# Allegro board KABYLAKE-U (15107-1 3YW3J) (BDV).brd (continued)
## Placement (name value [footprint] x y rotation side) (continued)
C410  SC22U6D3V3MX-1-DL-GP  [C603H40]  139.1 136.65 0 bottom
C411  SCD1U16V2KX-3DLGP  [C402H22]  175.42 135.51 180 bottom
C412  SC2D2U10V3KX-1DLGP-U  [C603H36]  145.96 130.05 0 bottom
C413  SC2D2U10V3KX-1DLGP-U  [C603H36]  131.35 129.92 0 bottom
C414  SCD1U16V2KX-3DLGP  [C402H22]  146.97 129.92 0 bottom
C415  SCD1U16V2KX-3DLGP  [C402H22]  130.59 126.62 180 bottom
C416  SC220P50V2KX-3DLGP  [C402H22]  106.97 126.11 270 bottom
C417  SCD1U16V2KX-3DLGP  [C402H22]  140.88 126.11 90 bottom
C418  SCD1U16V2KX-3DLGP  [C402H22]  128.81 125.73 180 bottom
C419  SCD1U16V2KX-3DLGP  [C402H22]  127.92 125.73 180 bottom
C420  SC4D7U6D3V3KX-DLGP  [C603H36]  140.88 125.09 90 bottom
C421  SC4D7U6D3V3KX-DLGP  [C603H36]  153.83 124.97 180 bottom
C422  SCD1U16V2KX-3DLGP  [C402H22]  152.81 124.84 180 bottom
C423  SCD1U16V2KX-3DLGP  [C402H22]  146.85 124.84 0 bottom
C424  SCD1U16V2KX-3DLGP  [C402H22]  145.96 124.84 0 bottom
C425  SCD01U50V2KX-1DLGP  [C402H22]  57.56 119.76 270 bottom
C426  SC10U6D3V3MX-DL-GP  [C603H36]  49.94 118.75 0 bottom
C427  SC1KP50V2KX-1DLGP  [C402H22]  60.1 118.36 0 bottom
C428  SC1U50V3KX-1-GP  [C603H36]  53.63 118.75 0 bottom
C429  SC1U50V3KX-1-GP  [C603H36]  52.36 118.75 0 bottom
C430  SCD1U16V2KX-3DLGP  [C402H22]  47.4 116.71 90 bottom
C431  SCD1U16V2KX-3DLGP  [C402H22]  47.4 115.82 90 bottom
C432  SCD1U16V2KX-3DLGP  [C402H22]  47.4 114.94 90 bottom
C433  SCD22U10V2KX-2-GP  [C402H22]  89.31 113.41 180 bottom
C434  SCD22U10V2KX-2-GP  [C402H22]  88.43 113.41 180 bottom
C435  SCD22U10V2KX-2-GP  [C402H22]  87.54 113.41 180 bottom
C436  SCD22U10V2KX-2-GP  [C402H22]  86.65 113.41 180 bottom
C437  SCD22U10V2KX-2-GP  [C402H22]  85.76 113.41 180 bottom
C438  SCD22U10V2KX-2-GP  [C402H22]  84.87 113.41 180 bottom
C439  SCD22U10V2KX-2-GP  [C402H22]  83.98 113.41 180 bottom
C440  SCD22U10V2KX-2-GP  [C402H22]  83.09 113.41 180 bottom
C441  SC10U10V5KX-2DLGP  [C805H50]  81.67 113.28 0 bottom
C442  SC10U10V5KX-2DLGP  [C805H50]  79.66 113.28 0 bottom
C443  SC1U50V3KX-1-GP  [C603H36]  76.74 111.63 0 bottom
C444  SC10U6D3V3MX-DL-GP  [C603H36]  75.47 111.63 0 bottom
C445  SC10U6D3V3MX-DL-GP  [C603H36]  74.2 111.63 0 bottom
C446  SC820P50V2KX-1-DL-GP  [C402H22]  47.28 111.63 90 bottom
C447  SC1U50V3KX-1-GP  [C603H36]  80.04 110.87 90 bottom
C448  SC820P50V2KX-1-DL-GP  [C402H22]  47.28 110.74 90 bottom
C449  SC10U6D3V3MX-DL-GP  [C603H36]  42.07 107.95 0 bottom
C450  SC10U6D3V3MX-DL-GP  [C603H36]  78.77 109.6 270 bottom
C451  SC10U6D3V3MX-DL-GP  [C603H36]  40.8 107.95 0 bottom
C453  SCD1U16V2KX-3DLGP  [C402H22]  41.94 110.74 0 bottom
C454  SCD1U16V2KX-3DLGP  [C402H22]  82.58 107.95 270 bottom
C455  SC4D7U6D3V3KX-DLGP  [C603H36]  80.81 107.06 180 bottom
C456  SC10U6D3V3MX-DL-GP  [C603H36]  79.28 107.06 0 bottom
C457  SC4D7U6D3V3KX-DLGP  [C603H36]  94.65 106.93 180 bottom
C458  SC4D7U6D3V3KX-DLGP  [C603H36]  92.87 106.93 180 bottom
C459  SCD1U16V2KX-3DLGP  [C402H22]  47.4 106.81 90 bottom
C460  SCD1U16V2KX-3DLGP  [C402H22]  89.31 106.63 0 bottom
C461  SCD1U16V2KX-3DLGP  [C402H22]  47.4 105.92 90 bottom
C462  SC1U10V2KX-1DLGP  [C402H22]  86.9 105.28 270 bottom
C463  SC4D7U6D3V3KX-DLGP  [C603H36]  83.85 104.9 0 bottom
C464  SC1U10V2KX-1DLGP  [C402H22]  81.57 104.78 180 bottom
C465  SC1U10V2KX-1DLGP  [C402H22]  79.54 104.78 180 bottom
C466  SC1U10V2KX-1DLGP  [C402H22]  78.65 104.78 180 bottom
C467  SC1U10V2KX-1DLGP  [C402H22]  77.76 104.01 0 bottom
C468  SC4D7U6D3V3KX-DLGP  [C603H36]  92.87 103.63 180 bottom
C469  SC1U50V3KX-1-GP  [C603H36]  47.02 103.38 90 bottom
C470  SC1U10V2KX-1DLGP  [C402H22]  91.85 103.25 0 bottom
C471  SC1U10V2KX-1DLGP  [C402H22]  90.84 103.25 0 bottom
C472  SC4D7U6D3V3KX-DLGP  [C603H36]  89.82 103.25 180 bottom
C473  SC4D7U6D3V3KX-DLGP  [C603H36]  88.55 103.25 180 bottom
C474  SC4D7U6D3V3KX-DLGP  [C603H36]  87.28 103.25 0 bottom
C475  SC4D7U6D3V3KX-DLGP  [C603H36]  85.5 103.25 0 bottom
C476  SC4D7U6D3V3KX-DLGP  [C603H36]  82.58 103.25 180 bottom
C477  SC4D7U6D3V3KX-DLGP  [C603H36]  80.55 103.25 180 bottom
C478  SC1U10V2KX-1DLGP  [C402H22]  77.76 102.11 180 bottom
C479  SC1U50V3KX-1-GP  [C603H36]  47.02 102.11 90 bottom
C480  SCD1U16V2KX-3DLGP  [C402H22]  62.26 100.84 90 bottom
C481  SCD1U16V2KX-3DLGP  [C402H22]  53.88 100.84 90 bottom
C482  SCD1U16V2KX-3DLGP  [C402H22]  50.58 100.84 270 bottom
C483  SC10U6D3V3MX-DL-GP  [C603H36]  47.02 100.84 90 bottom
C484  SC4D7U6D3V3KX-DLGP  [C603H36]  87.28 100.58 180 bottom
C485  SC4D7U6D3V3KX-DLGP  [C603H36]  85.5 100.58 180 bottom
C486  SC4D7U6D3V3KX-DLGP  [C603H36]  82.58 100.58 180 bottom
C487  SC4D7U6D3V3KX-DLGP  [C603H36]  80.55 100.58 180 bottom
C488  SCD1U16V2KX-3DLGP  [C402H22]  77.76 100.2 0 bottom
C489  SCD1U16V2KX-3DLGP  [C402H22]  62.26 99.95 90 bottom
C490  SCD1U16V2KX-3DLGP  [C402H22]  53.88 99.95 90 bottom
C491  SCD1U16V2KX-3DLGP  [C402H22]  47.4 99.69 90 bottom
C492  SCD1U16V2KX-3DLGP  [C402H22]  47.4 98.81 90 bottom
C493  SC4D7U6D3V3KX-DLGP  [C603H36]  88.31 97.92 0 bottom
C494  SC4D7U6D3V3KX-DLGP  [C603H36]  87.14 97.92 0 bottom
C495  SC4D7U6D3V3KX-DLGP  [C603H36]  85.5 97.92 0 bottom
C496  SC4D7U6D3V3KX-DLGP  [C603H36]  82.58 97.92 0 bottom
C497  SC4D7U6D3V3KX-DLGP  [C603H36]  80.55 97.92 0 bottom
C498  SC47U6D3V5MX-1DL-GP  [C805H54]  94.39 97.79 180 bottom
C499  SC22U6D3V5MX-2DLGP  [C805H54]  92.36 97.79 180 bottom
C500  SCD1U16V2KX-3DLGP  [C402H22]  90.84 97.79 180 bottom
C501  SCD1U16V2KX-3DLGP  [C402H22]  89.33 97.79 180 bottom
C502  SC1U50V3KX-1-GP  [C603H36]  47.02 97.66 90 bottom
C503  SCD1U16V2KX-3DLGP  [C402H22]  78.47 95.89 270 bottom
C504  SC1U50V3KX-1-GP  [C603H36]  47.02 95.63 90 bottom
C505  SC4D7U6D3V3KX-DLGP  [C603H36]  80.93 94.61 90 bottom
C506  SCD1U16V2KX-3DLGP  [C402H22]  47.4 94.61 90 bottom
C507  SC22U6D3V5MX-2DLGP  [C805H54]  95.79 94.23 180 bottom
C508  SCD1U16V2KX-3DLGP  [C402H22]  87.66 94.11 180 bottom
C509  SCD1U16V2KX-3DLGP  [C402H22]  86.27 94.11 180 bottom
C510  SCD1U16V2KX-3DLGP  [C402H22]  84.74 94.11 180 bottom
C511  SCD1U16V2KX-3DLGP  [C402H22]  83.85 94.11 180 bottom
C512  SCD1U16V2KX-3DLGP  [C402H22]  77.5 94.11 180 bottom
C513  SC1U50V3KX-1-GP  [C603H36]  89.19 93.98 180 bottom
C514  SC4D7U6D3V3KX-DLGP  [C603H36]  90.46 93.9 0 bottom
C515  SC1U50V3KX-1-GP  [C603H36]  94.14 93.85 180 bottom
C516  SCD1U16V2KX-3DLGP  [C402H22]  47.4 93.73 90 bottom
C517  SCD1U16V2KX-3DLGP  [C402H22]  47.4 92.71 90 bottom
C518  SC4D7U6D3V3KX-DLGP  [C603H36]  91.9 91.92 270 bottom
C519  SC1U50V3KX-1-GP  [C603H36]  91.9 90.75 90 bottom
C520  SCD1U16V2KX-3DLGP  [C402H22]  80.68 89.79 270 bottom
C521  SC1U50V3KX-1-GP  [C603H36]  80.81 88.77 270 bottom
C522  SC820P50V2KX-1-DL-GP  [C402H22]  47.12 88.65 90 bottom
C523  SC820P50V2KX-1-DL-GP  [C402H22]  47.12 87.76 90 bottom
C524  SC820P50V2KX-1-DL-GP  [C402H22]  47.12 86.87 90 bottom
C525  SC820P50V2KX-1-DL-GP  [C402H22]  47.12 85.98 90 bottom
C526  SC10U6D3V3MX-DL-GP  [C603H36]  50.45 82.68 90 bottom
C527  SCD1U50V3KX-DL-GP  [C603H35]  133.26 82.04 0 bottom
C528  SC100P50V2JN-3DLGP  [C402H22]  156.75 80.39 90 bottom
C529  SC10U6D3V3MX-DL-GP  [C603H36]  160.18 75.69 270 bottom
C530  SC1U50V3KX-1-GP  [C603H36]  59.47 75.44 90 bottom
C531  SC1U10V2KX-1DLGP  [C402H22]  160.18 74.42 270 bottom
C532  SCD1U16V2KX-3DLGP  [C402H22]  64.17 74.3 270 bottom
C533  SCD1U16V2KX-3DLGP  [C402H22]  57.06 72.9 270 bottom
C534  SCD1U16V2KX-3DLGP  [C402H22]  60.23 72.14 180 bottom
C535  SC100P50V2JN-3DLGP  [C402H22]  142.02 71.88 90 bottom
C536  SC10U10V5KX-2DLGP  [C805H50]  56.85 71.5 270 bottom
C537  SC10U10V5KX-2DLGP  [C805H50]  69.5 71.25 0 bottom
C538  SC1U6D3V2KX-GP  [C402H22]  134.27 68.45 0 bottom
C539  SC10U10V5KX-2DLGP  [C805H50]  57.69 68.2 90 bottom
C540  SCD1U16V2KX-3DLGP  [C402H22]  60.71 67.08 270 bottom
C541  SCD1U16V2KX-3DLGP  [C402H22]  65.69 66.8 90 bottom
C542  SCD1U16V2KX-3DLGP  [C402H22]  53.63 66.67 90 bottom
C543  SCD1U16V2KX-3DLGP  [C402H22]  68.36 66.42 0 bottom
C544  SCD1U50V3KX-DL-GP  [C603H35]  66.84 64.39 270 bottom
C545  SCD1U16V2KX-3DLGP  [C402H22]  137.96 65.28 0 bottom
C546  SCD1U16V2KX-3DLGP  [C402H22]  134.15 65.28 0 bottom
C547  SCD1U16V2KX-3DLGP  [C402H22]  132.11 65.28 180 bottom
C548  SCD1U10V2KX-5GP  [C402H22]  131.73 62.87 90 bottom
C549  SC10U10V5KX-2DLGP  [C805H50]  56.5 62.48 0 bottom
C550  SCD1U16V2KX-3DLGP  [C402H22]  132.49 61.98 90 bottom
C551  SC2D2U6D3V2MX-GP  [C402H22]  132.49 61.09 90 bottom
C552  SCD1U16V2KX-3DLGP  [C402H22]  53.63 60.33 90 bottom
C553  SCD1U16V2KX-3DLGP  [C402H22]  56.93 60.2 90 bottom
C554  SCD1U16V2KX-3DLGP  [C402H22]  65.57 59.51 270 bottom
C555  SC2D2U10V3KX-1DLGP-U  [C603H36]  135.54 59.31 90 bottom
C556  SCD1U16V2KX-3DLGP  [C402H22]  64.93 58.29 90 bottom
C557  SCD1U16V2KX-3DLGP  [C402H22]  53.63 58.29 90 bottom
C558  SC10U10V5KX-2DLGP  [C805H50]  65.18 56.9 270 bottom
C559  SCD1U16V2KX-3DLGP  [C402H22]  60.1 56.64 0 bottom
C560  SCD1U16V2KX-3DLGP  [C402H22]  57.18 56.64 180 bottom
C561  SCD1U16V2KX-3DLGP  [C402H22]  129.19 55.75 90 bottom
C562  SCD1U10V2KX-5GP  [C402H22]  144.81 55.5 270 bottom
C563  SCD1U16V2KX-3DLGP  [C402H22]  53.5 54.23 90 bottom
C564  SC1U16V3KX-2DLGP  [C603H36]  163.1 51.69 180 bottom
C565  SC10U6D3V2MX-2-GP  [C402-TO0D2H28]  119.29 50.14 180 bottom
C566  SCD1U10V2KX-5GP  [C402H22]  137.83 49.53 90 bottom
C567  SC10U6D3V2MX-2-GP  [C402-TO0D2H28]  119.29 48.36 0 bottom
C568  SCD1U10V2KX-5GP  [C402H22]  118.37 48.36 0 bottom
C569  SCD1U10V2KX-5GP  [C402H22]  130.21 47.62 180 bottom
C570  SCD1U25V2KX-1-DL-GP  [C402H22]  36.36 45.59 0 bottom
C571  SCD01U50V2KX-1DLGP  [C402H22]  50.05 44.7 0 bottom
C572  SC1U100V6KX-3-GP  [C1206H75]  32.42 41.53 270 bottom
C573  SC1U100V6KX-3-GP  [C1206H75]  26.58 41.53 90 bottom
C574  SC330P100V3JN-GP  [C603H36]  38.01 40.77 90 bottom
C575  SCD1U16V2KX-3DLGP  [C402H22]  142.02 40.01 180 bottom
C576  SC1U100V6KX-3-GP  [C1206H75]  32.42 39.24 270 bottom
C577  SC1U100V6KX-3-GP  [C1206H75]  26.58 39.24 90 bottom
C578  SCD1U16V2KX-3DLGP  [C402H22]  116.11 39.12 180 bottom
C579  SCD01U50V3KX-4DLGP  [C603H36]  162.85 37.21 180 bottom
C580  SCD01U50V3KX-4DLGP  [C603H36]  158.66 37.08 180 bottom
C581  SCD01U50V3KX-4DLGP  [C603H36]  156.75 37.08 180 bottom
C582  SCD01U50V3KX-4DLGP  [C603H36]  152.43 37.08 180 bottom
C583  SC1U100V6KX-3-GP  [C1206H75]  26.58 36.96 90 bottom
C584  SCD01U50V2KX-1DLGP  [C402H22]  134.15 34.67 90 bottom
C585  SC10U10V5KX-2DLGP  [C805H50]  133.64 33.15 90 bottom
C586  SCD1U16V2KX-3DLGP  [C402H22]  119.92 33.02 90 bottom
C587  SCD47U25V3KX-1-DL-GP  [C603H36]  29.5 29.21 0 bottom
C588  SCD1U16V2KX-3DLGP  [C402H22]  30.13 25.15 90 bottom
C589  SCD01U50V2KX-1DLGP  [C402H22]  64.3 24.77 270 bottom
C590  SCD1U50V3KX-DL-GP  [C603H35]  64.3 23.62 270 bottom
C591  SCD1U16V2KX-3DLGP  [C402H22]  30.13 23.24 270 bottom
C592  SCD1U16V2KX-3DLGP  [C402H22]  41.56 23.11 180 bottom
C593  SC1U10V2KX-1DLGP  [C402H22]  36.61 20.7 180 bottom
C594  SC33P50V2JN-3DLGP  [C402H22]  124.75 20.19 180 bottom
C595  SC100P3KV8JN-4-GP  [C1808H87]  65.18 18.16 0 bottom
C596  SC4D7U6D3V3KX-DLGP  [C603H36]  39.66 17.65 180 bottom
C597  SCD1U16V2KX-3DLGP  [C402H22]  37.63 17.53 180 bottom
C598  SCD1U16V2KX-3DLGP  [C402H22]  36.74 17.53 180 bottom
C599  SCD1U16V2KX-3DLGP  [C402H22]  35.85 17.53 180 bottom
C600  SCD1U16V2KX-3DLGP  [C402H22]  40.42 15.88 90 bottom
C601  SCD1U16V2KX-3DLGP  [C402H22]  35.85 15.62 0 bottom
C602  SCD1U16V2KX-3DLGP  [C402H22]  39.63 14.07 90 bottom
C603  SCD1U16V2KX-3DLGP  [C402H22]  36.23 13.97 270 bottom
C604  SC1U10V2KX-1DLGP  [C402H22]  129.07 13.72 0 bottom
C605  SCD1U16V2KX-3DLGP  [C402H22]  88.93 13.34 0 bottom
C606  SC1U10V2KX-1DLGP  [C402H22]  121.32 12.95 180 bottom
C607  SC1U25V3KX-1-DLGP  [C603H36]  32.42 12.9 180 bottom
C609  SCD1U16V2KX-3DLGP  [C402H22]  39.53 12.57 0 bottom
C610  SC1U10V2KX-1DLGP  [C402H22]  38.64 12.57 0 bottom
C611  SCD1U16V2KX-3DLGP  [C402H22]  37.75 12.57 0 bottom
C612  SCD1U16V2KX-3DLGP  [C402H22]  36.74 12.57 0 bottom
C614  SC4D7U6D3V3KX-DLGP  [C603H36]  31.78 10.97 90 bottom
C615  SC1U6D3V2KX-DLGP  [C402H22]  122.84 10.03 90 bottom
C620  SC1U10V2KX-1DLGP  [C402H22]  32.16 7.57 90 bottom
C621  SCD1U16V2KX-3DLGP  [C402H22]  39.2 7.39 90 bottom
C623  SC10U10V5KX-2DLGP  [C805H50]  26.96 6.1 180 bottom
C624  SC1U10V2KX-1DLGP  [C402H22]  44.23 6.05 180 bottom
C627  SCD1U16V2KX-3DLGP  [C402H22]  88.68 81.66 0 bottom
C628  SC1U10V2KX-1DLGP  [C402H22]  34.83 108.08 180 bottom
C629  SCD022U16V2KX-3DLGP  [C402H22]  34.83 106.05 0 bottom
C630  SC4D7U6D3V3KX-DLGP  [C603H36]  40.8 110.74 0 bottom
C631  SC4D7U6D3V3KX-DLGP  [C603H36]  59.22 71.75 0 bottom
C632  SC4D7U6D3V3KX-DLGP  [C603H36]  69.38 66.04 0 bottom
C633  SC1U10V2KX-1DLGP  [C402H22]  75.6 224.79 180 top
C634  SCD1U16V2KX-3DLGP  [C402H22]  79.03 145.29 0 bottom
C635  SC8P50V2DN-1DL-GP  [C402H22]  111.54 206.38 315 bottom
C636  SC2200P50V2KX-2DLGP  [C402H22]  110.27 207.65 315 bottom
C637  SCD1U16V2KX-3DLGP  [C402H22]  160.94 31.62 270 bottom
C638  SCD1U16V2KX-3DLGP  [C402H22]  160.82 26.92 270 bottom
CN1  ACES-CON4-37-GP  [88459-047N]  85.76 125.09 225 bottom
CONVT1  CLX-CON10-10-GP  [CI1410M1HRL-NH]  25 36.65 270 top
CPU1  SKYLAKE-U-GP  [BGA1356M4224-U2H52]  83 165 270 top
D1  1SS355-4-GP  [SOD323AKH38]  13.88 220.47 180 top
D2  1SS355-4-GP  [SOD323AKH38]  121.55 106.3 90 top
D3  TVLST2304BD0-GP  [SOT-6H58]  172.37 105.92 270 top
D4  AZ2015-01H-GP  [SOD523AKH28]  162.34 88.14 90 top
D5  1SS355-4-GP  [SOD323AKH38]  86.77 72.11 180 top
D6  1SS355-4-GP  [SOD323AKH38]  88.81 72.11 180 top
D7  BAS40C-2-GP  [SOT-23-9H44]  112.56 48.39 180 top
D8  TVLST2304BD0-GP  [SOT-6H58]  106.46 32.26 180 top
D9  1SS355-4-GP  [SOD323AKH38]  125.13 30.1 90 top
D10  BZX84-C6V8-GP  [SOT-23-9H44]  114.97 26.16 180 top
D11  BAT54C-12-GP  [SOT-23-9H44]  120.05 26.16 0 top
D12  P6SMB27A-1-GP  [DO214AAAK-1121H97]  60.36 22.86 180 top
D13  SP3010-04UTG-GP  [SLP2510P8-1H22]  106.59 21.59 0 top
D14  SP3010-04UTG-GP  [SLP2510P8-1H22]  106.71 11.81 180 top
D15  AZ5325-01FDR7G-GP  [D402H24]  139.48 164.97 90 bottom
D16  BAT54C-11-GP  [SOT23-2D4-312H44]  35.09 140.08 180 bottom
D17  BAT54A-7-F-2-GP  [SOT23-2D4-312H48]  95.41 113.54 0 bottom
D18  BAT54A-7-F-2-GP  [SOT23-2D4-312H48]  133 57.15 90 bottom
D19  1SS355-4-GP  [SOD323AKH38]  139.33 57.53 270 bottom
D20  BAV99GP-GP  [SOT23-2D4-312H48]  58.83 36.2 0 bottom
D21  BX310F-R1-00000-GP  [D4724AKH44]  33.94 34.42 0 bottom
D22  AZ5725-01FDR7G-GP  [SOD882-10D6-1H20]  26.83 24 180 bottom
D23  1SS355-4-GP  [SOD323AKH38]  23.66 143.51 270 bottom
D24  1SS355-4-GP  [SOD323AKH38]  91.09 120.02 90 top
D25  AZ5325-01FDR7G-GP  [D402H24]  106.33 128.14 270 bottom
DCIN1  DC-JACK373-GP  [JPDA3B1-V4501-7F]  53.25 25.53 270 top
DCIN2  ACES-CONN14G-GP  [88314-077N]  55.64 33.67 180 top
DIMM1  DDR4-260P-18-GP  [40-42271-26001RHF]  135.3 158.9 270 top
DIMM2  DDR4-260P-46-GP  [40-42275-26001RHF]  150.5 158.9 270 top
F1  POLYSW-1D5A6V-12-GP  [POLYSW-2114H30]  160.18 189.87 90 top
F2  POLYSW-1D5A6V-12-GP  [POLYSW-2114H30]  162.72 186.94 180 top
F3  FUSE-3A32V-26-GP  [FUSE-1608H22]  45.63 39.88 270 top
F4  POLYSW-2A6V-7-GP  [POLYSW-2114H30]  6.26 210.82 0 bottom
F6  POLYSW-1D5A6V-12-GP  [POLYSW-2114H30]  118.4 35.43 90 bottom
F7  POLYSW-1D5A6V-12-GP  [POLYSW-2114H30]  24.8 6.1 0 bottom
FANC3  FOX-CON4-30-GP  [HF1804H]  14 211 270 top
GPU1  N16S-GM-S-A2-GP  [BGA595M23H83]  83 100 180 top
H1  HOLE237R158-GP  [HOLE237R158]  94.38 192.31 180 top
H2  HOLE237R158-GP  [HOLE237R158]  62.39 165.12 180 top
H3  HOLE237R158-GP  [HOLE237R158]  94.38 137.93 180 top
H4  HOLE237R158-GP  [HOLE237R158]  69 123.75 180 top
H5  HOLE237R158-GP  [HOLE237R158]  94.39 76.25 180 top
H6  GEN8D5X8R5X4D5-8-F-A-GP  [GEN8D5X8R5X4D5-8-F-A]  165 225 270 top
H7  GEN315R138-8-F-A-1-GP  [GEN315R138-8-F-A-1]  5 160 180 top
H9  GEN8D5X8R5X4D5-8-F-A-GP  [GEN8D5X8R5X4D5-8-F-A]  25 49.15 180 top
H10  GEN315R178-8-F-A-3-GP  [GEN315R178-8-F-A-1]  165 20 180 top
H11  GEN315R138-8-F-A-2-S-GP  [GEN315R138-8-F-A-2-S]  172.5 64.43 180 top
HDD1  SKT-SATA7P-184-GP-U  [15-02070-5A61-A]  12 142 270 top
HDMI1  SKT-HDMI22-12-GP  [SKT-HDMI22-150077]  113.99 37.03 270 top
HDMI2  SKT-HDMI22-12-GP  [SKT-HDMI22-150077]  113.99 14.03 270 top
HDMI3  ARG-CON20-GP  [LVDFH-02004-TP00]  118.69 37.07 270 top
HDMI4  ARG-CON20-GP  [LVDFH-02004-TP00]  118.7 14.07 270 top
HS6  STF256R109H99-GP  [STF256R109H99]  144.25 214 180 top
JMP1  PIN-CONN6A-S3-GP  [21S-92-03GB16]  112.43 110.74 90 top
KBC1  NPCE285PA0DX-1-GP  [LQFP128H63]  136.94 56.9 180 top
L1  COIL-50OHM-GP  [L125100-4P-1H24]  16.54 173.86 180 top
L2  COIL-50OHM-GP  [L125100-4P-1H24]  16.54 170.43 180 top
L3  COIL-50OHM-GP  [L125100-4P-1H24]  17.81 150.62 270 top
L4  COIL-50OHM-GP  [L125100-4P-1H24]  17.94 144.02 270 top
L5  FILTER-4P-123-GP  [L125100-4P-1H36]  164.75 116.33 180 top
L6  FILTER-4P-123-GP  [L125100-4P-1H36]  164.75 114.17 180 top
L7  MHC1608S181NBP-GP  [L603H38]  102.9 101.85 0 top
L8  MHC1608S300QBP-GP  [L603H38]  100.87 103 0 top
L9  FILTER-4P-123-GP  [L125100-4P-1H36]  164.63 97.28 180 top
L10  FILTER-4P-123-GP  [L125100-4P-1H36]  164.63 95.12 180 top
L11  HCB1608KF-800T30-GP  [L603H38]  164.88 88.27 180 top
L12  MCB1005S121FBP-GP  [L402H24]  156.75 68.91 90 top
L13  MCB1005S121FBP-GP  [L402H24]  160.69 66.8 90 top
L14  MHC1608S221NBP-GP  [L603H38]  151.16 47.5 180 top
L15  HCB2012KF-601T20-GP  [L20125H42]  153.58 38.99 0 top
L16  HCB2012KF-601T20-GP  [L20125H42]  155.61 38.99 0 top
L17  HCB2012KF-601T20-GP  [L20125H42]  159.8 38.99 0 top
L18  HCB2012KF-601T20-GP  [L20125H42]  161.83 38.99 0 top
L19  MCB1005S121FBP-GP  [L402H24]  83.35 37.34 180 top
L20  MCB1005S121FBP-GP  [L402H24]  84.49 37.34 180 top
L21  IND-33UH-85-GP  [L8080-6020H158]  38.13 34.54 270 top
L23  MHC1608S300QBP-GP  [L603H38]  95.41 102.11 0 bottom
L24  MHC1608S181NBP-GP  [L603H38]  57.44 69.82 90 bottom
L25  MHC1608S181NBP-GP  [L603H38]  65.31 65.79 270 bottom
L26  MHC1608S181NBP-GP  [L603H38]  54.01 62.36 90 bottom
L27  MHC1608S181NBP-GP  [L603H38]  62.01 59.56 270 bottom
L28  MHC1608S181NBP-GP  [L603H38]  62.01 58.29 270 bottom
L29  -  [0R0805-PAD]  117.51 38.35 180 bottom
L30  BLM15BD102SN1D-GP  [L402H22]  55.66 33.91 90 bottom
L31  MHC1608S181NBP-GP  [L603H38]  71.92 71.25 270 bottom
L32  MHC1608S181NBP-GP  [L603H38]  70.65 66.04 180 bottom
LED1  LED-O-23-GP  [LED1608AKH30]  142.53 38.99 0 top
LOUT1  AUDIO-JK419-GP  [JAC331-0140A8B-9H]  76.93 37.66 90 top
LPC1  FOX-CONN14A-S1-GP  [HL5507F]  114.59 55.63 0 top
LVDS1  ACES-CON30-21-GP  [50524-0300N-001]  36.8 95 270 top
MEMCD1  SKT-SDCARD-52-GP  [156-5101902601]  174.65 144.79 90 top
NGFF1  SKT-MINI67P-3-GP-U1  [2199230-7]  116 214 270 top
NOREF  -  []  133 212.09 0 top
NOREF#2  *  [unnamed#2]  171.63 8.45 0 top
NOREF#3  *  [unnamed#2]  98.46 81.03 0 top
NOREF#4  -  []  0 0 0 top
NOREF#5  -  []  155.48 220.09 0 top
NOREF#6  -  [unnamed#2]  166.53 216.03 0 top
NOREF#7  -  []  56.46 128.17 0 top
NOREF#8  *  [unnamed#2]  5.05 6.01 0 top
NOREF#9  -  [unnamed#2]  9.56 12.19 0 top
NOREF#10  -  []  -64.42 3.3 0 top
NOREF#11  -  [unnamed#2]  178.22 223.03 0 top
NOREF#12  *  [unnamed#2]  147.23 29.97 0 top
NOREF#13  *  [unnamed#2]  114.71 60.83 0 top
NOREF#14  *  [unnamed#2]  65.06 140.97 0 top
NOREF#15  -  []  0 113.25 0 top
NOREF#16  *  [unnamed#2]  106.54 198.78 0 top
NOREF#17  *  [unnamed#2]  178.33 217.98 0 top
NOREF#18  -  []  131.94 226.95 0 top
NOREF#19  -  [unnamed#2]  11.57 4.95 0 top
NOREF#20  -  [unnamed#2]  171.63 4.95 0 top
NOREF#21  -  []  105.82 193.04 0 top
NOREF#22  -  []  -10 0 0 top
NOREF#23  -  [unnamed#2]  3.34 226.69 0 top
NOREF#24  *  [unnamed#2]  8.8 218.82 0 top
NOREF#25  *  [unnamed#2]  145.7 39.24 0 top
NOREF#26  *  [unnamed#2]  167.42 207.9 0 top
NOREF#27  *  [unnamed#2]  178.33 217.98 180 bottom
NOREF#28  *  [unnamed#2]  156.88 224.03 180 bottom
NOREF#29  *  [unnamed#2]  5.05 6.01 180 bottom
NOREF#30  -  []  122.46 182.37 90 bottom
NOREF#31  -  []  178.45 28.4 90 bottom
NOREF#32  *  [unnamed#2]  171.63 8.45 180 bottom
NOREF#33  *  [unnamed#2]  6 224.16 180 bottom
NOREF#34  -  []  153.83 220.22 180 bottom
NOREF#35  *  [unnamed#2]  155.1 29.97 180 bottom
ODD1  SKT-SATA7P-184-GP-U  [15-02070-5A61-A]  8.4 177 270 top
P1  0R0402-PAD-2-GP  [0R0402-PAD-1]  42.96 19.18 90 top
P2  0R0402-PAD-2-GP  [0R0402-PAD-1]  42.96 18.16 90 top
P3  0R0402-PAD-2-GP  [0R0402-PAD-1]  42.96 16.76 90 top
P4  0R0402-PAD-2-GP  [0R0402-PAD-1]  42.96 15.75 90 top
PC1  SCD1U50V3KX-DL-GP  [C603H35]  88.81 224.03 180 top
PC2  SC22U6D3V5MX-2DLGP  [C805H54]  64.35 211.07 180 top
PC3  SC22U6D3V5MX-2DLGP  [C805H54]  66.28 211.07 180 top
PC4  SC1500P50V2KX-2-DL-GP  [C402H22]  22 208.03 0 top
PC5  SC10U10V5KX-2DLGP  [C805H50]  87.79 207.77 0 top
PC6  SC1KP50V2KX-1DLGP  [C402H22]  20.56 207.52 270 top
PC7  SC1U50V3KX-1-GP  [C603H36]  90.97 206.88 270 top
PC8  SCD01U50V2KX-1DLGP  [C402H22]  24.54 204.6 0 top
PC9  SCD1U25V2KX-1-DL-GP  [C402H22]  25.43 204.6 0 top
PC10  SCD01U50V2KX-1DLGP  [C402H22]  26.32 204.6 0 top
PC11  SC1U50V3KX-1-GP  [C603H36]  27.85 203.96 0 top
PC12  SCD015U25V2KX-DLGP  [C402H22]  21.7 203.63 0 top
PC13  SC15P50V2JN-DL-GP  [C402H22]  23.15 203.55 270 top
PC14  SC22U6D3V5MX-2DLGP  [C805H54]  64.93 202.82 0 top
PC15  SC22U6D3V5MX-2DLGP  [C805H54]  66.96 202.82 0 top
PC16  SC22U6D3V5MX-2DLGP  [C805H54]  68.99 202.82 0 top
PC17  SC22U6D3V5MX-2DLGP  [C805H54]  71.03 202.82 0 top
PC18  SC1KP50V2KX-1DLGP  [C402H22]  23.12 201.65 90 top
PC19  SC2D2U10V3KX-1DLGP-U  [C603H36]  32.67 201.17 90 top
PC20  SC470P50V2KX-3DLGP  [C402H22]  23.15 200.74 270 top
PC21  SC22U6D3V5MX-2DLGP  [C805H54]  72.68 200.03 270 top
PC22  SC22U6D3V5MX-2DLGP  [C805H54]  72.25 197.23 180 top
PC23  SC2200P50V2KX-2DLGP  [C402H22]  31.38 196.06 0 top
PC24  SC1KP50V2KX-1DLGP  [C402H22]  21.62 195.2 180 top
PC25  SC10U6D3V2MX-2-GP  [C402-TO0D2H28]  82.46 194.69 90 top
PC26  SC470P50V2KX-3DLGP  [C402H22]  20.1 193.8 270 top
PC27  SC10U6D3V2MX-2-GP  [C402-TO0D2H28]  82.46 193.68 90 top
PC28  SC1KP50V2KX-1DLGP  [C402H22]  31.4 192.91 90 top
PC29  SC470P50V2KX-3DLGP  [C402H22]  33.31 192.91 270 top
PC30  SC10U6D3V2MX-2-GP  [C402-TO0D2H28]  82.46 192.66 90 top
PC31  SCD015U25V2KX-DLGP  [C402H22]  27.97 192.41 0 top
PC32  SCD033U25V2KX-1-GP  [C402H22]  28.86 192.41 0 top
PC33  SC1KP50V2KX-1DLGP  [C402H22]  20.86 192.15 270 top
PC34  SC10U6D3V2MX-2-GP  [C402-TO0D2H28]  82.46 191.64 90 top
PC35  SC10U6D3V2MX-2-GP  [C402-TO0D2H28]  82.46 190.63 90 top
PC36  SCD1U25V2KX-1-DL-GP  [C402H22]  23.66 190.5 0 top
PC37  SC22U6D3V5MX-2DLGP  [C805H54]  75.32 190.5 0 top
PC38  SC10U6D3V2MX-2-GP  [C402-TO0D2H28]  82.46 189.61 90 top
PC39  SC10U6D3V2MX-2-GP  [C402-TO0D2H28]  82.46 188.59 90 top
PC40  SC22U6D3V5MX-2DLGP  [C805H54]  47.79 187.58 180 top
PC41  SC1KP50V2KX-1DLGP  [C402H22]  25.56 186.18 0 top
PC42  SC22U6D3V5MX-2DLGP  [C805H54]  57.82 184.53 0 top
PC43  SC22U6D3V5MX-2DLGP  [C805H54]  59.85 184.53 0 top
PC44  SC22U6D3V5MX-2DLGP  [C805H54]  61.88 184.53 0 top
PC45  SC10U6D3V2MX-2-GP  [C402-TO0D2H28]  56.68 182.25 90 top
PC46  SC22U6D3V5MX-2DLGP  [C805H54]  57.82 179.96 180 top
PC47  SC22U6D3V5MX-2DLGP  [C805H54]  59.85 179.96 180 top
PC48  SC22U6D3V5MX-2DLGP  [C805H54]  61.88 179.96 180 top
PC49  SC10U6D3V2MX-2-GP  [C402-TO0D2H28]  57.69 175.64 180 top
PC50  SC10U6D3V2MX-2-GP  [C402-TO0D2H28]  58.71 175.64 180 top
PC51  SC10U6D3V2MX-2-GP  [C402-TO0D2H28]  59.72 175.64 180 top
PC52  SC22U6D3V5MX-2DLGP  [C805H54]  48.93 172.85 0 top
PC53  SC22U6D3V5MX-2DLGP  [C805H54]  50.96 172.85 0 top
PC54  SC22U6D3V5MX-2DLGP  [C805H54]  52.99 172.85 0 top
PC55  SC22U6D3V5MX-2DLGP  [C805H54]  55.02 172.85 0 top
PC56  SC22U6D3V5MX-2DLGP  [C805H54]  57.06 172.85 0 top
PC57  SC22U6D3V5MX-2DLGP  [C805H54]  59.09 172.85 0 top
PC58  SC22U6D3V5MX-2DLGP  [C805H54]  61.12 172.85 0 top
PC59  SC1U10V2KX-1DLGP  [C402H22]  163.79 171.78 90 top
PC60  SC22U6D3V5MX-2DLGP  [C805H54]  44.61 171.45 180 top
PC61  SC22U6D3V5MX-2DLGP  [C805H54]  46.57 171.45 180 top
PC62  SC10U6D3V2MX-2-GP  [C402-TO0D2H28]  53.88 169.16 180 top
PC63  SC10U6D3V2MX-2-GP  [C402-TO0D2H28]  54.9 169.16 180 top
PC64  SC10U6D3V2MX-2-GP  [C402-TO0D2H28]  55.91 169.16 180 top
PC65  SC10U6D3V2MX-2-GP  [C402-TO0D2H28]  56.93 169.16 180 top
PC66  SC10U6D3V2MX-2-GP  [C402-TO0D2H28]  57.95 169.16 180 top
PC67  SC1U10V2KX-1DLGP  [C402H22]  158.4 168.15 180 top
PC68  SC1U10V2KX-1DLGP  [C402H22]  160.43 168.15 180 top
PC69  SC10U25V5KX-DL-GP  [C805H58]  30.51 165.48 0 top
PC70  SCD22U25V3KX-DL-GP  [C603H36]  27.59 164.85 90 top
PC71  SC22U6D3V5MX-2DLGP  [C805H54]  56.37 162.99 0 top
PC72  SC10U6D3V2MX-2-GP  [C402-TO0D2H28]  53.7 162.94 0 top
PC73  SC10U6D3V2MX-2-GP  [C402-TO0D2H28]  46.52 162.43 0 top
PC74  SC2D2U10V3KX-1DLGP-U  [C603H36]  23.15 161.42 180 top
PC75  SC18P50V2JN-1DLGP  [C402H22]  22.26 154.94 270 top
PC76  SC1KP50V2KX-1DLGP  [C402H22]  22.82 150.37 180 top
PC77  SCD1U50V3KX-DL-GP  [C603H35]  27.97 149.73 180 top
PC78  SCD1U16V2KX-3DLGP  [C402H22]  56.68 141.86 0 top
PC79  SC10U6D3V2MX-2-GP  [C402-TO0D2H28]  39.02 135.51 0 top
PC80  SC10U6D3V2MX-2-GP  [C402-TO0D2H28]  40.04 135.51 0 top
PC81  SC10U6D3V3MX-DL-GP  [C603H36]  90.46 128.78 0 top
PC82  SC10U6D3V3MX-DL-GP  [C603H36]  97.95 127.13 90 top
PC83  SC10U6D3V3MX-DL-GP  [C603H36]  97.95 125.86 270 top
PC84  SC1U50V3KX-1-GP  [C603H36]  86.24 125.73 270 top
PC85  SC100P50V2JN-3DLGP  [C402H22]  96.86 124.21 0 top
PC86  SCD1U16V2KX-3DLGP  [C402H22]  87.16 123.57 180 top
PC87  SC22P50V2JN-4DLGP  [C402H22]  88.55 120.02 0 top
PC88  SC100P50V2JN-3DLGP  [C402H22]  106.21 107.06 90 top
PC89  SCD1U16V2KX-3DLGP  [C402H22]  118.52 104.78 90 top
PC90  SCD1U16V2KX-3DLGP  [C402H22]  118.52 103.89 90 top
PC91  SC1U50V3KX-1-GP  [C603H36]  118.14 101.73 90 top
PC92  SCD1U16V2KX-3DLGP  [C402H22]  126.65 101.22 0 top
PC93  SC10U10V5KX-2DLGP  [C805H50]  106.33 98.68 0 top
PC94  SC10U10V5KX-2DLGP  [C805H50]  108.36 98.68 0 top
PC95  SCD1U50V3KX-DL-GP  [C603H35]  110.4 98.68 0 top
PC96  SC10U10V5KX-2DLGP  [C805H50]  113.19 98.68 0 top
PC97  SC10U10V5KX-2DLGP  [C805H50]  115.22 98.68 0 top
PC98  SC22U6D3V5MX-2DLGP  [C805H54]  113.19 93.98 180 top
PC99  SC1KP50V2KX-1DLGP  [C402H22]  131.1 84.2 90 top
PC100  SC10U25V5KX-DL-GP  [C805H58]  141.38 83.19 180 top
PC101  SC1KP50V2KX-1DLGP  [C402H22]  113.57 79.38 90 top
PC102  SC10U25V5KX-DL-GP  [C805H58]  116.37 79.25 270 top
PC103  SC22U6D3V5MX-2DLGP  [C805H54]  102.01 76.33 180 top
PC104  SC22U6D3V5MX-2DLGP  [C805H54]  104.05 76.33 180 top
PC105  SC10U25V5KX-DL-GP  [C805H58]  32.67 74.42 180 top
PC106  SC22P50V2JN-4DLGP  [C402H22]  121.95 74.04 270 top
PC107  SCD1U50V3KX-DL-GP  [C603H35]  36.48 72.9 180 top
PC108  SC10U25V5KX-DL-GP  [C805H58]  34.83 72.77 180 top
PC109  SC2200P50V2KX-2DLGP  [C402H22]  37.5 72.77 180 top
PC110  SCD01U50V2KX-1DLGP  [C402H22]  119.67 70.36 0 top
PC111  SCD1U16V2KX-3DLGP  [C402H22]  120.56 70.36 0 top
PC112  SCD1U50V3KX-DL-GP  [C603H35]  114.84 70.23 180 top
PC113  SC1U50V3KX-1-GP  [C603H36]  117.38 70.23 0 top
PC114  SC22U6D3V5MX-2DLGP  [C805H54]  102.01 70.1 0 top
PC115  SC22U6D3V5MX-2DLGP  [C805H54]  104.05 70.1 0 top
PC116  SCD1U50V3KX-DL-GP  [C603H35]  34.86 67.34 0 top
PC117  SC10U25V5KX-DL-GP  [C805H58]  36.41 66.9 0 top
PC118  SC10U25V5KX-DL-GP  [C805H58]  40.93 50.67 270 top
PC119  SC470P50V2KX-3DLGP  [C402H22]  38.01 47.24 270 top
PC120  SCD47U25V3KX-1-DL-GP  [C603H36]  45.12 46.86 0 top
PC121  SCD1U50V3KX-DL-GP  [C603H35]  47.05 46.74 270 top
PC122  SCD1U50V3KX-DL-GP  [C603H35]  47.05 45.57 270 top
PC123  SC220P50V2KX-3DLGP  [C402H22]  43.59 43.43 180 top
PC124  SCD01U50V2KX-1DLGP  [C402H22]  44.48 43.43 180 top
PC125  SCD1U50V3KX-DL-GP  [C603H35]  154.19 26.77 180 top
PC126  SC22P50V2JN-4DLGP  [C402H22]  156.24 24.77 0 top
PC127  SCD1U50V3KX-DL-GP  [C603H35]  148.75 23.37 270 top
PC128  SC4D7U6D3V3KX-DLGP  [C603H36]  156.88 22.1 90 top
PC129  SCD1U16V2KX-3DLGP  [C402H22]  149 20.83 270 top
PC130  SC22P50V2JN-4DLGP  [C402H22]  155.74 20.45 180 top
PC131  SC1KP50V2KX-1DLGP  [C402H22]  138.46 19.81 180 top
PC132  SCD1U50V3KX-DL-GP  [C603H35]  151.8 16.89 180 top
PC133  SC1U50V3KX-1-GP  [C603H36]  137.57 13.08 0 top
PC134  SC1U50V3KX-1-GP  [C603H36]  147.99 12.32 90 top
PC135  SC1KP50V2KX-1DLGP  [C402H22]  97.06 224.92 0 bottom
PC136  SC10U25V5KX-DL-GP  [C805H58]  88.76 224.16 0 bottom
PC137  SC10U25V5KX-DL-GP  [C805H58]  86.82 224.16 0 bottom
PC138  SC10U25V5KX-DL-GP  [C805H58]  84.87 224.16 0 bottom
PC139  SC10U25V5KX-DL-GP  [C805H58]  41.05 219.33 0 bottom
PC140  SC10U25V5KX-DL-GP  [C805H58]  39.02 219.33 0 bottom
PC141  SC1U50V3KX-1-GP  [C603H36]  84.74 217.04 0 bottom
PC142  SC1U50V3KX-1-GP  [C603H36]  81.19 217.04 0 bottom
PC143  SC22U6D3V5MX-2DLGP  [C805H54]  62.64 216.03 0 bottom
PC144  SC22U6D3V5MX-2DLGP  [C805H54]  60.61 216.03 0 bottom
PC145  SC100P50V2JN-3DLGP  [C402H22]  139.48 205.74 0 bottom
PC146  SC1U50V3KX-1-GP  [C603H36]  128.68 204.34 90 bottom
PC147  SC22U6D3V5MX-2DLGP  [C805H54]  65.44 213.11 270 bottom
PC148  SCD1U16V2KX-L-GP  [C402H22]  79.79 212.98 90 bottom
PC149  SC1KP50V2KX-1DLGP  [C402H22]  42.58 212.98 90 bottom
PC151  SCD1U50V3KX-DL-GP  [C603H35]  91.6 212.34 90 bottom
PC152  SC10U25V5KX-DL-GP  [C805H58]  40.29 211.96 180 bottom
PC153  SC10U25V5KX-DL-GP  [C805H58]  38.26 211.96 180 bottom
PC154  SC10U10V5KX-2DLGP  [C805H50]  132.11 211.07 90 bottom
PC155  SC10U10V5KX-2DLGP  [C805H50]  132.11 209.04 90 bottom
PC156  SC22U6D3V5MX-2DLGP  [C805H54]  65.44 211.07 270 bottom
PC157  SCD1U16V2KX-3DLGP  [C402H22]  126.78 210.57 90 bottom
PC158  SC150P50V2JN-3DLGP  [C402H22]  23.3 210.06 270 bottom
PC159  SC220P50V2KX-3DLGP  [C402H22]  18.58 209.63 180 bottom
PC160  SC330P50V2KX-3-DL-GP  [C402H22]  23.3 209.17 270 bottom
PC161  SC2200P50V2KX-2DLGP  [C402H22]  21.88 209.17 180 bottom
PC162  SC22U6D3V5MX-2DLGP  [C805H54]  65.44 209.04 270 bottom
PC163  SC18P50V2JN-1-GP  [C402H22]  79.15 208.79 0 bottom
PC164  SCD1U25V2KX-1-DL-GP  [C402H22]  28.48 208.79 90 bottom
PC165  SCD1U25V2KX-1-DL-GP  [C402H22]  26.45 208.79 90 bottom
PC166  SC33P50V2JN-3DLGP  [C402H22]  21.24 207.77 90 bottom
PC167  SC22U6D3V5MX-2DLGP  [C805H54]  65.44 207.01 270 bottom
PC168  SCD047U25V2KX-GP  [C402H22]  84.11 206.38 180 bottom
PC169  SCD22U25V3KX-DL-GP  [C603H36]  32.42 206.38 90 bottom
PC170  SC10U10V5KX-2DLGP  [C805H50]  87.54 205.61 180 bottom
PC171  SC10U10V5KX-2DLGP  [C805H50]  85.5 205.61 180 bottom
PC172  SC10U10V5KX-2DLGP  [C805H50]  141.13 203.45 270 bottom
PC173  SC22U6D3V5MX-2DLGP  [C805H54]  65.44 204.98 270 bottom
PC174  SC470P50V2KX-3DLGP  [C402H22]  19.34 204.6 270 bottom
PC175  SC1U10V2KX-1DLGP  [C402H22]  146.46 204.09 90 bottom
PC176  SC10U10V5KX-2DLGP  [C805H50]  141.13 201.42 270 bottom
PC177  SC22U6D3V5MX-2DLGP  [C805H54]  65.44 202.95 270 bottom
PC179  SCD22U25V3KX-DL-GP  [C603H36]  32.77 201.42 90 bottom
PC180  SCD015U25V2KX-DLGP  [C402H22]  19.72 200.53 270 bottom
PC181  SC6800P25V2KX-1DLGP  [C402H22]  19.72 199.64 90 bottom
PC182  SCD22U25V3KX-DL-GP  [C603H36]  32.39 198.96 270 bottom
PC183  SC22P50V2JN-4DLGP  [C402H22]  158.15 198.25 180 bottom
PC184  SC10U25V5KX-DL-GP  [C805H58]  40.88 198.12 0 bottom
PC185  SC10U25V5KX-DL-GP  [C805H58]  38.95 198.12 0 bottom
PC186  SC10U25V5KX-DL-GP  [C805H58]  37.02 198.12 0 bottom
PC187  SC10U25V5KX-DL-GP  [C805H58]  35.09 198.12 0 bottom
PC188  SC1KP50V3KX-DLGP  [C603H36]  43.21 197.99 90 bottom
PC189  SCD1U25V2KX-1-DL-GP  [C402H22]  31.53 195.2 180 bottom
PC190  SCD01U50V2KX-1DLGP  [C402H22]  30.51 195.2 180 bottom
PC191  SC15P50V2JN-DL-GP  [C402H22]  29.62 195.2 180 bottom
PC192  SC1KP50V2KX-1DLGP  [C402H22]  27.59 195.2 180 bottom
PC193  SC22U6D3V5MX-2DLGP  [C805H54]  79.41 194.69 315 bottom
PC194  SC470P50V2KX-3DLGP  [C402H22]  26.7 194.36 0 bottom
PC195  SC22U6D3V5MX-2DLGP  [C805H54]  47.66 187.58 0 bottom
PC196  SC22U6D3V5MX-2DLGP  [C805H54]  45.63 187.58 0 bottom
PC197  SC22U6D3V5MX-2DLGP  [C805H54]  60.36 184.53 180 bottom
PC198  SC22U6D3V5MX-2DLGP  [C805H54]  58.33 184.53 180 bottom
PC199  SC22U6D3V5MX-2DLGP  [C805H54]  86.01 183.64 270 bottom
PC200  SC22U6D3V3MX-1-DL-GP  [C603H40]  106.84 180.72 90 bottom
PC201  SC22U6D3V3MX-1-DL-GP  [C603H40]  60.13 180.09 0 bottom
PC202  SC22U6D3V5MX-2DLGP  [C805H54]  58.58 180.09 0 bottom
PC203  SC10U25V5KX-DL-GP  [C805H58]  25.94 178.18 0 bottom
PC204  SC10U25V5KX-DL-GP  [C805H58]  23.91 178.18 0 bottom
PC205  SC10U25V5KX-DL-GP  [C805H58]  21.88 178.18 0 bottom
PC206  SC10U25V5KX-DL-GP  [C805H58]  19.85 178.18 0 bottom
PC207  SC22U6D3V5MX-2DLGP  [C805H54]  81.82 177.42 270 bottom
PC208  SC22U6D3V5MX-2DLGP  [C805H54]  72.8 177.42 90 bottom
PC209  SC22U6D3V3MX-1-DL-GP  [C603H40]  96.68 175.9 0 bottom
PC210  SC10U6D3V2MX-2-GP  [C402-TO0D2H28]  76.36 175.77 180 bottom
PC211  SC10U6D3V2MX-2-GP  [C402-TO0D2H28]  59.47 175.64 0 bottom
PC212  SC10U6D3V2MX-2-GP  [C402-TO0D2H28]  58.45 175.64 0 bottom
PC213  SC22U6D3V5MX-2DLGP  [C805H54]  81.82 175.39 270 bottom
PC214  SC10U6D3V2MX-2-GP  [C402-TO0D2H28]  71.84 174.62 0 bottom
PC215  SC10U6D3V2MX-2-GP  [C402-TO0D2H28]  70.82 174.62 0 bottom
PC216  SC10U6D3V2MX-2-GP  [C402-TO0D2H28]  69.81 174.62 0 bottom
PC217  SC10U6D3V2MX-2-GP  [C402-TO0D2H28]  68.79 174.62 0 bottom
PC218  SC22U6D3V5MX-2DLGP  [C805H54]  81.82 173.35 270 bottom
PC219  SC22U6D3V5MX-2DLGP  [C805H54]  85.12 172.97 0 bottom
PC220  SC22U6D3V5MX-2DLGP  [C805H54]  52.79 172.85 180 bottom
PC221  SC22U6D3V5MX-2DLGP  [C805H54]  50.86 172.85 180 bottom
PC222  SC22U6D3V5MX-2DLGP  [C805H54]  48.93 172.85 180 bottom
PC223  SC22U6D3V5MX-2DLGP  [C805H54]  56.65 172.82 180 bottom
PC224  SC22U6D3V5MX-2DLGP  [C805H54]  54.72 172.82 180 bottom
PC225  SC22U6D3V3MX-1-DL-GP  [C603H40]  58.2 172.06 180 bottom
PC226  SC22U6D3V5MX-2DLGP  [C805H54]  46.57 171.45 0 bottom
PC227  SC22U6D3V5MX-2DLGP  [C805H54]  44.61 171.45 0 bottom
PC228  SC22U6D3V5MX-2DLGP  [C805H54]  42.58 171.45 0 bottom
PC229  SC10U6D3V2MX-2-GP  [C402-TO0D2H28]  77.25 170.81 180 bottom
PC230  SC10U6D3V2MX-2-GP  [C402-TO0D2H28]  76.23 170.81 180 bottom
PC231  SC22U6D3V5MX-2DLGP  [C805H54]  82.84 170.56 180 bottom
PC232  SC22U6D3V5MX-2DLGP  [C805H54]  80.81 170.56 180 bottom
PC233  SC22U6D3V5MX-2DLGP  [C805H54]  78.77 170.56 180 bottom
PC234  SC10U6D3V2MX-2-GP  [C402-TO0D2H28]  57.95 169.16 0 bottom
PC235  SC10U6D3V2MX-2-GP  [C402-TO0D2H28]  56.93 169.16 0 bottom
PC236  SC10U6D3V2MX-2-GP  [C402-TO0D2H28]  55.91 169.16 0 bottom
PC237  SC22U6D3V5MX-2DLGP  [C805H54]  54.39 168.4 0 bottom
PC238  SC10U6D3V2MX-2-GP  [C402-TO0D2H28]  87.79 167 270 bottom
PC239  SC10U6D3V2MX-2-GP  [C402-TO0D2H28]  87.79 165.94 270 bottom
PC240  SC10U25V5KX-DL-GP  [C805H58]  30.51 165.48 180 bottom
PC241  SC22U6D3V3MX-1-DL-GP  [C603H40]  85.66 164.62 180 bottom
PC242  SC22U6D3V5MX-2DLGP  [C805H54]  69.38 164.47 180 bottom
PC243  SC22U6D3V3MX-1-DL-GP  [C603H40]  84.31 163.86 180 bottom
PC244  SC22U6D3V3MX-1-DL-GP  [C603H40]  83.14 163.86 180 bottom
PC245  SC22U6D3V3MX-1-DL-GP  [C603H40]  79.64 163.86 180 bottom
PC246  SC22U6D3V3MX-1-DL-GP  [C603H40]  78.47 163.86 180 bottom
PC247  SC10U6D3V2MX-2-GP  [C402-TO0D2H28]  67.85 163.58 0 bottom
PC248  SC22U6D3V5MX-2DLGP  [C805H54]  56.29 163.07 180 bottom
PC249  SC10U6D3V2MX-2-GP  [C402-TO0D2H28]  54.77 162.94 180 bottom
PC250  SC10U6D3V2MX-2-GP  [C402-TO0D2H28]  80.68 161.16 0 bottom
PC251  SC22U6D3V3MX-1-DL-GP  [C603H40]  94.65 157.99 270 bottom
PC252  SC1U10V2KX-1DLGP  [C402H22]  25.31 152.02 90 bottom
PC253  SC10U25V5KX-DL-GP  [C805H58]  30.26 150.5 0 bottom
PC254  SC10U25V5KX-DL-GP  [C805H58]  28.23 150.5 0 bottom
PC255  SC1KP50V2KX-1DLGP  [C402H22]  33.69 150.11 90 bottom
PC256  SC1U10V2KX-1DLGP  [C402H22]  37.5 139.06 180 bottom
PC257  SC22P50V2JN-4DLGP  [C402H22]  125.28 106.32 0 bottom
PC258  SC100P50V2JN-3DLGP  [C402H22]  124.39 106.32 180 bottom
PC259  SC1U50V3KX-1-GP  [C603H36]  130.34 104.52 0 bottom
PC260  SC47P50V2JN-5DLGP  [C402H22]  122.33 104.52 90 bottom
PC261  SC4D7U6D3V3KX-DLGP  [C603H36]  133.76 100.58 270 bottom
PC262  SCD1U16V2KX-3DLGP  [C402H22]  121.7 99.26 90 bottom
PC263  SCD1U50V3KX-DL-GP  [C603H35]  133.76 98.3 90 bottom
PC264  SC2700P50V2KX-1-DL-GP  [C402H22]  122.08 97.28 90 bottom
PC265  SC1U10V2KX-1DLGP  [C402H22]  129.7 94.61 180 bottom
PC266  SCD01U25V2KX-L1-GP  [C402H22]  128.81 94.61 180 bottom
PC267  SC1KP50V2KX-1DLGP  [C402H22]  123.6 94.61 180 bottom
PC268  SC5600P50V3KX-DL-GP  [C603H36]  119.54 94.36 180 bottom
PC269  SC10U25V5KX-DL-GP  [C805H58]  136.94 82.04 0 bottom
PC270  SC10U25V5KX-DL-GP  [C805H58]  134.91 82.04 0 bottom
PC271  SC10U25V5KX-DL-GP  [C805H58]  116.37 79.25 90 bottom
PC272  SCD1U50V3KX-DL-GP  [C603H35]  116.49 77.6 90 bottom
PC273  SC1KP50V2KX-1DLGP  [C402H22]  39.78 73.53 90 bottom
PC274  SCD1U16V2KX-3DLGP  [C402H22]  121.95 72.01 270 bottom
PC275  SC1U25V3KX-1-GP  [C603H36]  26.58 70.28 270 bottom
PC276  SC10P50V2JN-4DLGP  [C402H22]  32.67 67.18 0 bottom
PC277  SC10P50V2JN-4DLGP  [C402H22]  32.67 65.28 180 bottom
PC278  SC470P50V2KX-3DLGP  [C402H22]  32.67 63.37 0 bottom
PC279  SCD1U25V2KX-1-DL-GP  [C402H22]  41.05 52.2 90 bottom
PC280  SC10U25V5KX-DL-GP  [C805H58]  40.93 50.67 90 bottom
PC281  SCD1U50V3KX-DL-GP  [C603H35]  43.21 49.12 270 bottom
PC282  SC1U10V2KX-1DLGP  [C402H22]  38.01 47.37 270 bottom
PC283  SCD1U50V3KX-DL-GP  [C603H35]  46.13 46.61 0 bottom
PC284  SCD1U50V3KX-DL-GP  [C603H35]  35.34 45.21 180 bottom
PC285  SCD1U25V2KX-1-DL-GP  [C402H22]  36.36 43.69 180 bottom
PC286  SC10U25V5KX-DL-GP  [C805H58]  143.29 27.05 90 bottom
PC287  SC10U25V5KX-DL-GP  [C805H58]  143.29 25.02 90 bottom
PC288  SC10U25V5KX-DL-GP  [C805H58]  133.38 23.65 270 bottom
PC289  SCD1U16V2KX-3DLGP  [C402H22]  152.18 24.26 180 bottom
PC290  SC4D7U6D3V3KX-DLGP  [C603H36]  148.75 23.37 90 bottom
PC291  SCD1U50V3KX-DL-GP  [C603H35]  143.29 23.37 90 bottom
PC292  SCD1U50V3KX-DL-GP  [C603H35]  133.38 27.13 270 bottom
PC293  SCD1U16V2KX-3DLGP  [C402H22]  153.58 20.95 90 bottom
PC294  SC1KP50V2KX-1DLGP  [C402H22]  138.46 21.08 0 bottom
PC295  SC1U10V2KX-1DLGP  [C402H22]  39.66 5.97 180 bottom
PC296  SC1KP50V2KX-1DLGP  [C402H22]  33.18 162.69 90 bottom
PC297  SC10U25V5KX-DL-GP  [C805H58]  133.38 25.58 270 bottom
PC299  SCD1U25V2KX-1-DL-GP  [C402H22]  36.74 211.84 180 bottom
PC302  SCD1U25V2KX-1-DL-GP  [C402H22]  31.66 149.73 0 bottom
PC303  SC10U25V5KX-DL-GP  [C805H58]  26.2 171.58 180 bottom
PC304  SC10U25V5KX-DL-GP  [C805H58]  43.09 219.33 0 bottom
PD1  1N4148WS-7-F-GP  [SOD323AKH42]  35.47 48.77 90 top
PD2  1SS355-4-GP  [SOD323AKH38]  134.25 94.36 270 bottom
PD3  RB520SM-30T2R-GP  [D1608-035030AKH28]  38.01 48.77 270 bottom
PG1  GAP-CLOSE-PWR-3-GP  [GAP-CLOSE-PWR-3]  54.64 210.95 180 top
PG2  GAP-CLOSE-PWR-3-GP  [GAP-CLOSE-PWR-3]  58.71 210.95 0 top
PG3  GAP-CLOSE-PWR-3-GP  [GAP-CLOSE-PWR-3]  23.02 209.68 90 top
PG4  GAP-CLOSE-PWR-3-GP  [GAP-CLOSE-PWR-3]  20.23 208.79 0 top
PG5  GAP-CLOSE-PWR-3-GP  [GAP-CLOSE-PWR-3]  54.64 199.77 180 top
PG6  GAP-CLOSE-PWR-3-GP  [GAP-CLOSE-PWR-3]  58.71 199.77 0 top
PG7  GAP-CLOSE-PWR-3-GP  [GAP-CLOSE-PWR-3]  30.89 191.64 270 top
PG8  GAP-CLOSE-PWR-3-GP  [GAP-CLOSE-PWR-3]  31.91 191.64 270 top
PG9  GAP-CLOSE-PWR-3-GP  [GAP-CLOSE-PWR-3]  20.35 190.88 270 top
PG10  GAP-CLOSE-PWR-3-GP  [GAP-CLOSE-PWR-3]  21.37 190.88 270 top
PG11  GAP-CLOSE-PWR-3-GP  [GAP-CLOSE-PWR-3]  40.17 180.21 180 top
PG12  GAP-CLOSE-PWR-3-GP  [GAP-CLOSE-PWR-3]  44.36 180.21 0 top
PG13  GAP-CLOSE-PWR-3-GP  [GAP-CLOSE-PWR-3]  39.91 164.08 180 top
PG14  GAP-CLOSE-PWR-3-GP  [GAP-CLOSE-PWR-3]  42.96 164.08 0 top
PG15  GAP-CLOSE-PWR-3-GP  [GAP-CLOSE-PWR-3]  38.79 66.67 180 top
PG16  GAP-CLOSE-PWR-3-GP  [GAP-CLOSE-PWR-3]  38.79 64.9 180 top
PG17  GAP-CLOSE-PWR-3-GP  [GAP-CLOSE-PWR-3]  62.26 43.94 180 top
PG18  GAP-CLOSE-PWR-3-GP  [GAP-CLOSE-PWR-3]  62.26 42.16 180 top
PG19  GAP-CLOSE-PWR-3-GP  [GAP-CLOSE-PWR-3]  147.23 13.72 270 top
PG20  GAP-CLOSE-PWR-3-GP  [GAP-CLOSE-PWR-3]  145.32 4.7 180 top
PG21  GAP-CLOSE-PWR-3-GP  [GAP-CLOSE-PWR-3]  155.74 24.51 270 bottom
PG22  GAP-CLOSE-PWR-3-GP  [GAP-CLOSE-PWR-3]  149.89 24.89 0 bottom
PG23  GAP-CLOSE-PWR-3-GP  [GAP-CLOSE-PWR-3]  137.57 12.32 270 bottom
PL1  IND-1UH-94-GP-U  [L686647-127318H119]  97.57 216.66 0 top
PL2  IND-D15UH-13-GP  [L112100-2030H158]  56.68 210.95 90 top
PL3  IND-D15UH-13-GP  [L112100-2030H158]  56.68 199.77 90 top
PL4  IND-D15UH-13-GP  [L112100-2030H158]  42.2 180.21 90 top
PL5  IND-D47UH-33-GP-U  [L686647-127318H119]  41.44 164.08 90 top
PL6  IND-1UH-93-GP  [L115100-2030H158]  43.85 151.76 90 top
PL7  IND-D36UH-19-GP  [L115100-2H158]  117.33 86.11 270 top
PL8  IND-1UH-94-GP-U  [L686647-127318H119]  109.58 74.3 270 top
PL9  IND-5D6UH-45-GP-U  [L686647-127318H119]  40.67 59.31 180 top
PL10  IND-2D2UH-122-GP-U  [L686647-127318H119]  133.13 16.26 180 top
PL11  IND-2D2UH-122-GP-U  [L686647-127318H119]  142.78 16.26 0 top
PL13  VARISTOR-5D5V-29-GP  [VARISTOR-402-H24]  31.66 67.18 0 bottom
PL14  VARISTOR-5D5V-29-GP  [VARISTOR-402-H24]  31.66 65.28 180 bottom
PL15  VARISTOR-5D5V-29-GP  [VARISTOR-402-H24]  31.66 63.37 0 bottom
PQ1  MMBT3906-4-GP  [SOT23CBE2D4H44]  35.72 51.69 0 top
PQ2  2N7002A-7-GP  [SOT23DGS2D4H48]  37.12 44.96 270 top
PQ3  2N7002A-7-GP  [SOT23DGS2D4H48]  52.36 42.29 90 top
PQ4  2N7002KDW-GP  [SOT-363H44]  56.42 41.91 270 top
PQ5  2N7002KDW-1-GP  [SOT-363H44]  89.82 40.39 0 top
PQ6  LMUN5212T1G-GP  [SOT323CBE2D2H40]  91.85 34.04 180 top
PQ7  LMUN5112T1G-GP  [SOT323EBC2D2H40]  89.95 29.34 0 top
PQ8  2N7002KDW-GP  [SOT-363H44]  25.69 66.93 180 bottom
PQ9  NTJD512NT1G-GP  [SOT-363H44]  72.8 66.67 0 bottom
PQ10  2N7002K-2-GP  [SOT23DGS2D4H44]  52.36 44.83 90 bottom
PQ11  NTJD512NT1G-GP  [SOT-363H44]  56.42 41.91 90 bottom
PR1  NTC-100K-12-GP-U  [NTC-402H22-U]  52.74 217.3 270 top
PR2  NTC-220K-GP-U  [NTC-402H22-U]  55.28 217.3 270 top
PR3  -  [0R0805-PAD]  90.58 210.57 270 top
PR4  2D2R3-1-U-GP  [R603H22]  32.29 209.55 0 top
PR5  1KR2F-3-GP  [R402H16]  29.12 208.66 90 top
PR6  -  [0R0805-PAD]  90.58 208.53 270 top
PR7  2K43R2F-GP  [R402H16]  23.02 208.03 0 top
PR8  1KR2F-3-GP  [R402H16]  23.15 204.49 270 top
PR9  14KR2F-GP  [R402H16]  29.62 204.47 270 top
PR10  29K4R2F-GP  [R402H16]  29.62 203.45 270 top
PR11  32K4R2F-1-GP  [R402H16]  23.15 202.61 270 top
PR12  12K4R2F-GP  [R402H16]  28.48 200.28 270 top
PR13  84K5R2F-GP  [R402H16]  23.15 199.72 90 top
PR14  51KR2F-L-GP  [R402H16]  23.15 198.7 270 top
PR15  1K24R2F-GP  [R402H16]  30.36 196.06 0 top
PR16  4K99R2F-L-GP  [R402H16]  32.39 196.06 180 top
PR17  2KR2F-3-GP  [R402H16]  33.41 196.06 0 top
PR18  2KR2F-3-GP  [R402H16]  19.59 195.2 180 top
PR19  2K61R2F-1-GP  [R402H16]  20.61 195.2 0 top
PR20  1KR2F-3-GP  [R402H16]  22.64 195.2 180 top
PR21  7K5R3F-2-GP  [R603H22]  26.96 192.79 0 top
PR22  100R2F-L1-GP-U  [R402H14]  23.66 192.41 180 top
PR23  1KR2F-3-GP  [R402H16]  24.67 192.41 180 top
PR24  13K7R2F-GP  [R402H16]  29.88 192.41 0 top
PR25  45D3R2F-L-GP  [R402H16]  24.67 190.5 0 top
PR26  0R2J-2-GP  [R402H16]  25.69 190.5 0 top
PR27  2D2R5J-1-GP  [R805H24]  29.12 186.94 270 top
PR28  NTC-100K-12-GP-U  [NTC-402H22-U]  34.2 186.31 90 top
PR29  NTC-100K-12-GP-U  [NTC-402H22-U]  42.45 186.31 90 top
PR30  0R2J-2-GP  [R402H16]  13.37 186.06 180 top
PR31  0R2J-2-GP  [R402H16]  165.39 175.13 0 top
PR32  -  [0R0805-PAD]  20.86 172.59 0 top
PR33  -  [0R0805-PAD]  22.89 172.59 0 top
PR34  -  [0R0805-PAD]  24.93 172.59 0 top
PR35  -  [0R0805-PAD]  27.72 170.81 90 top
PR36  -  [0R0805-PAD]  27.72 168.78 90 top
PR37  NTC-100K-12-GP-U  [NTC-402H22-U]  40.42 168.53 90 top
PR38  2D2R3-1-U-GP  [R603H22]  23.15 164.08 180 top
PR39  10KR2F-2-GP  [R402H16]  22.26 153.92 270 top
PR40  23K7R2F-GP  [R402H16]  22.26 152.91 90 top
PR41  470KR2F-GP  [R402H16]  22.26 151.89 90 top
PR42  0R2J-2-GP  [R402H16]  21.88 150.37 0 top
PR43  2D2R3-1-U-GP  [R603H22]  24.77 149 180 top
PR44  10KR2J-3-GP  [R402H16]  22.26 148.84 270 top
PR45  10KR2J-3-GP  [R402H16]  22.26 147.57 90 top
PR46  0R0402-PAD-2-GP  [0R0402-PAD-1]  22.26 146.56 270 top
PR47  0R2J-2-GP  [R402H16]  25.18 146.3 90 top
PR48  0R0402-PAD-2-GP  [0R0402-PAD-1]  22.26 145.54 270 top
PR49  -  [0R0805-PAD]  26.2 141.48 180 top
PR50  -  [0R0805-PAD]  28.13 141.48 180 top
PR51  -  [0R0805-PAD]  30.06 141.48 180 top
PR52  -  [0R0805-PAD]  32.01 141.48 180 top
PR53  12K4R2F-GP  [R402H16]  95.92 124.21 0 top
PR54  10KR2J-3-GP  [R402H16]  86.14 123.57 0 top
PR55  10KR2F-2-GP  [R402H16]  95.92 122.3 0 top
PR57  0R2J-2-GP  [R402H16]  95.28 119.63 90 top
PR58  1KR2J-1-GP  [R402H16]  95.28 120.65 270 top
PR59  31K6R2F-GP  [R402H16]  106.21 108.08 90 top
PR60  100KR2F-L1-GP  [R402H16]  107.73 107.57 180 top
PR61  10R2F-L-GP  [R402H14]  106.21 106.05 90 top
PR62  0R0402-PAD-1-GP  [0R0402-PAD]  118.52 105.79 270 top
PR63  10KR2J-3-GP  [R402H16]  121.19 104.78 270 top
PR64  -  [0R0805-PAD]  105.44 104.52 270 top
PR65  10KR2J-3-GP  [R402H16]  121.19 103.76 90 top
PR66  10KR2J-3-GP  [R402H16]  118.52 102.87 270 top
PR67  -  [0R0805-PAD]  105.44 102.49 270 top
PR68  5K9R3F-3-GP  [R603H22]  125.51 100.84 180 top
PR69  10KR2J-3-GP  [R402H16]  98.84 96.27 90 top
PR70  2D2R5J-1-GP  [R805H24]  126.78 84.58 270 top
PR71  2D2R5J-1-GP  [R805H24]  108.72 79.25 270 top
PR72  2D2R5J-1-GP  [R805H24]  122.21 78.74 90 top
PR73  100KR2F-L1-GP  [R402H16]  121.95 77.09 270 top
PR74  10KR2F-2-GP  [R402H16]  121.95 76.07 90 top
PR75  NTC-100K-12-GP-U  [NTC-402H22-U]  125.51 75.95 270 top
PR76  -  [0R0402-PAD]  100.11 75.69 270 top
PR77  6K98R2F-GP  [R402H16]  121.95 75.06 270 top
PR78  -  [0R0402-PAD]  100.11 74.68 270 top
PR79  -  [0R0402-PAD]  100.11 73.66 270 top
PR80  0R2J-2-GP  [R402H16]  121.95 73.03 90 top
PR81  -  [0R0402-PAD]  100.11 72.64 270 top
PR82  0R0402-PAD-2-GP  [0R0402-PAD-1]  121.95 72.01 90 top
PR83  -  [0R0402-PAD]  100.11 71.63 270 top
PR84  10KR2J-3-GP  [R402H16]  121.95 70.87 270 top
PR85  -  [0R0402-PAD]  100.11 70.61 270 top
PR86  0R0603-PAD-1-GP-U  [0R0603-PAD-U]  116.11 70.23 0 top
PR87  2D2R3-1-U-GP  [R603H22]  118.65 70.23 180 top
PR88  D01R3721F-GP-U  [R3720H40]  41.05 65.79 180 top
PR89  100KR2J-1-GP  [R402H16]  36.23 58.04 0 top
PR90  1MR2J-1-GP  [R402H16]  35.85 54.1 270 top
PR91  0R2J-2-GP  [R402H16]  40.29 48.77 270 top
PR92  107KR2F-GP  [R402H16]  49.33 45.21 90 top
PR93  -  [0R0402-PAD]  40.04 44.83 90 top
PR94  56K2R2F-2-GP  [R402H16]  49.33 44.2 270 top
PR95  33KR2F-GP  [R402H16]  40.04 43.81 90 top
PR96  47KR2F-GP  [R402H16]  45.5 43.43 180 top
PR97  110KR2F-GP  [R402H16]  46.52 43.43 180 top
PR98  D01R3721F-GP-U  [R3720H40]  64.55 43.05 180 top
PR99  49K9R2F-L-GP  [R402H16]  59.85 42.93 270 top
PR100  100KR2J-1-GP  [R402H16]  38.13 42.67 90 top
PR101  100KR2J-1-GP  [R402H16]  48.42 42.67 0 top
PR102  100KR2J-1-GP  [R402H16]  49.44 42.67 0 top
PR103  100KR2J-1-GP  [R402H16]  141.77 49.15 0 bottom
PR104  309KR2F-GP  [R402H16]  46.26 41.15 270 top
PR105  3K3R2J-3-GP  [R402H16]  140.75 61.85 180 bottom
PR106  3K3R2J-3-GP  [R402H16]  141.77 61.85 180 bottom
PR107  100KR2J-1-GP  [R402H16]  61.5 40.64 0 top
PR108  1KR2J-1-GP  [R402H16]  92.11 39.62 0 top
PR109  0R5J-5-GP  [R805H24]  68.74 37.97 180 top
PR110  0R5J-5-GP  [R805H24]  70.77 37.97 180 top
PR111  3K3R6J-GP  [R1206H28]  89.19 33.91 180 top
PR112  2D2R5J-1-GP  [R805H24]  151.8 27.13 270 top
PR113  82KR2F-1-GP  [R402H16]  155.99 27.05 180 top
PR114  2D2R5J-1-GP  [R805H24]  148.9 26.85 0 top
PR115  10KR2F-2-GP  [R402H16]  158.78 25.27 90 top
PR116  6K65R2F-GP  [R402H16]  157.26 24.77 0 top
PR117  15K4R2F-GP  [R402H16]  156.75 20.45 180 top
PR118  10KR2F-2-GP  [R402H16]  157.84 19.48 0 top
PR119  84K5R2F-GP  [R402H16]  154.85 18.92 90 top
PR120  2D2R5J-1-GP  [R805H24]  150.15 16.64 0 top
PR121  2D2R5J-1-GP  [R805H24]  137.96 16.26 180 top
PR122  -  [0R0805-PAD]  82.08 223.65 270 bottom
PR123  -  [0R0805-PAD]  82.08 221.62 270 bottom
PR124  2D2R5J-1-GP  [R805H24]  97.32 221.23 0 bottom
PR125  143KR2F-GP  [R402H16]  85.89 217.3 0 bottom
PR126  10KR2J-3-GP  [R402H16]  90.71 217.04 270 bottom
PR127  5D1R3F-GP  [R603H22]  82.46 217.04 0 bottom
PR128  -  [0R0805-PAD]  32.55 216.79 0 bottom
PR129  -  [0R0805-PAD]  30.51 216.79 0 bottom
PR130  -  [0R0805-PAD]  28.48 216.79 0 bottom
PR131  0R0402-PAD-1-GP  [0R0402-PAD]  83.6 216.66 0 bottom
PR132  100KR2J-1-GP  [R402H16]  80.04 216.66 180 bottom
PR133  750KR2F-GP  [R402H16]  79.03 216.66 180 bottom
PR134  -  [0R0805-PAD]  35.47 215.82 270 bottom
PR135  21K5R2F-GP  [R402H16]  140.5 205.74 0 bottom
PR136  2D2R5J-1-GP  [R805H24]  90.2 215.52 270 bottom
PR137  10KR2F-2-GP  [R402H16]  141.51 205.74 180 bottom
PR138  -  [0R0805-PAD]  137.32 209.04 270 bottom
PR139  -  [0R0805-PAD]  137.32 211.07 270 bottom
PR141  0R0402-PAD-1-GP  [0R0402-PAD]  79.79 214 270 bottom
PR142  -  [0R0805-PAD]  35.47 213.87 270 bottom
PR144  2D2R5J-1-GP  [R805H24]  45.88 212.98 90 bottom
PR145  110KR3F-GP  [R603H22]  25.76 211.71 270 bottom
PR146  0R0402-PAD-1-GP  [0R0402-PAD]  126.78 211.58 270 bottom
PR147  560KR2F-GP  [R402H16]  23.86 211.46 180 bottom
PR148  220KR2F-GP  [R402H16]  22.84 211.46 0 bottom
PR149  0R0402-PAD-1-GP  [0R0402-PAD]  80.3 210.69 180 bottom
PR150  2D2R5J-1-GP  [R805H24]  90.58 210.57 270 bottom
PR151  115KR3F-GP  [R603H22]  30.39 210.57 180 bottom
PR152  909R2F-GP  [R402H16]  31.53 210.19 0 bottom
PR153  3K57R2F-GP  [R402H16]  29.12 210.19 0 bottom
PR154  10R2F-L-GP  [R402H14]  28.1 210.19 180 bottom
PR155  10R2F-L-GP  [R402H14]  26.96 210.19 180 bottom
PR156  3K57R2F-GP  [R402H16]  25.94 210.19 0 bottom
PR157  12K7R2F-GP  [R402H16]  33.05 209.8 90 bottom
PR158  1KR2F-3-GP  [R402H16]  19.59 209.63 0 bottom
PR159  10KR2F-2-GP  [R402H16]  126.78 209.55 270 bottom
PR160  4K7R2F-GP  [R402H16]  20.86 209.17 180 bottom
PR161  20KR2F-L-GP  [R402H16]  81.19 208.79 180 bottom
PR162  15K8R2F-GP  [R402H16]  80.17 208.79 0 bottom
PR163  -  [0R0805-PAD]  90.58 208.53 90 bottom
PR164  14K7R2F-L-GP  [R402H16]  23.3 208.15 270 bottom
PR165  1KR2F-3-GP  [R402H16]  26.45 207.77 270 bottom
PR166  49D9R2F-GP  [R402H16]  19.34 207.77 90 bottom
PR167  2D2R3-1-U-GP  [R603H22]  32.42 207.65 90 bottom
PR168  100KR2F-L1-GP  [R402H16]  19.34 206.76 90 bottom
PR169  -  [0R0805-PAD]  90.58 206.5 90 bottom
PR170  -  [0R0402-PAD]  82.96 206.38 180 bottom
PR171  30K9R2F-GP  [R402H16]  19.34 205.61 270 bottom
PR172  20KR2F-L-GP  [R402H16]  19.34 203.58 270 bottom
PR173  2D2R3F-L-GP  [R603H24]  32.77 200.18 270 bottom
PR174  13K7R2F-GP  [R402H16]  19.72 198.63 270 bottom
PR175  -  [0R0805-PAD]  139.1 198.5 180 bottom
